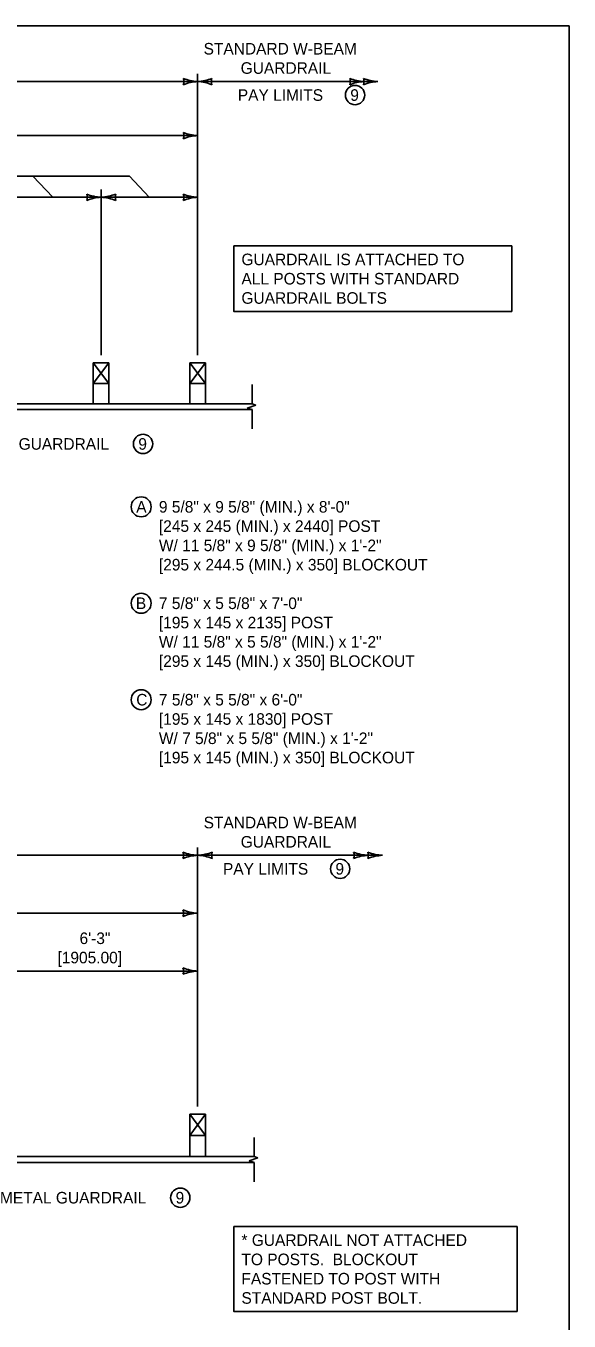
# Model space of a CAD drawing. Extents: x 49991.4 to 50021, y 49987.6 to 50011.4.
# Drawn here: x 50013.94 to 50016.75, y 49992.28 to 49999 of the extents above; entities that cross this region are included whole.
import ezdxf

# ---------------------------------------------------------------- set-up
doc = ezdxf.new("R2010")
doc.units = 0
for name, color, linetype in [('Level 1', 7, 'Continuous'), ('Level 2', 7, 'Continuous'), ('Level 3', 7, 'Continuous'), ('Level 6', 7, 'Continuous')]:
    doc.layers.add(name, color=color, linetype=linetype)

msp = doc.modelspace()

# ---------------------------------------------------------------- linework, layer by layer
at = {"layer": 'Level 1'}
for p, q in [((50014.2865, 49997.2528), (50014.2865, 49997.146)), ((50014.2865, 49997.2528), (50014.3665, 49997.2528)), ((50014.3665, 49997.2528), (50014.2865, 49997.146)), ((50014.2865, 49997.2528), (50014.3665, 49997.146)), ((50014.3665, 49997.2528), (50014.3665, 49997.146)), ((50014.7867, 49997.2528), (50014.7867, 49997.146)), ((50014.7867, 49997.2528), (50014.8668, 49997.2528)), ((50014.8668, 49997.2528), (50014.7867, 49997.146)), ((50014.7867, 49997.2528), (50014.8668, 49997.146)), ((50014.8668, 49997.2528), (50014.8668, 49997.146)), ((50014.2865, 49997.1464), (50014.2865, 49997.0393)), ((50014.2865, 49997.146), (50014.3665, 49997.146)), ((50014.3665, 49997.0393), (50014.3665, 49997.146)), ((50014.7867, 49997.1464), (50014.7867, 49997.0393)), ((50014.7867, 49997.146), (50014.8668, 49997.146)), ((50014.8668, 49997.0393), (50014.8668, 49997.146)), ((50010.7212, 49997.0393), (50015.1097, 49997.0393)), ((50010.6183, 49997.0101), (50015.1097, 49997.0101)), ((50014.8682, 49993.3576), (50014.7856, 49993.3576)), ((50014.7856, 49993.3576), (50014.7856, 49993.1371)), ((50014.7856, 49993.2474), (50014.8682, 49993.3576)), ((50014.7856, 49993.3576), (50014.8682, 49993.2474)), ((50014.8682, 49993.1371), (50014.8682, 49993.3576)), ((50014.7856, 49993.2474), (50014.8682, 49993.2474)), ((50010.1008, 49993.1371), (50015.1199, 49993.1371)), ((50010.1008, 49993.1071), (50015.1199, 49993.1071))]:
    msp.add_line(p, q, dxfattribs=at)
msp.add_lwpolyline([(49999.3835, 49998.9992), (50016.7501, 49998.9992), (50016.7501, 49987.7988), (49999.3835, 49987.7988)], close=True, dxfattribs=at)
at = {"layer": 'Level 2'}
for points in [[(50015.0136, 49997.8586), (50016.4533, 49997.8586), (50016.4533, 49997.5186), (50015.0136, 49997.5186)], [(50015.0136, 49992.7744), (50016.4809, 49992.7744), (50016.4809, 49992.3344), (50015.0136, 49992.3344)]]:
    msp.add_lwpolyline(points, close=True, dxfattribs=at)
for centre, radius in [((50015.6417, 49998.6408), 0.05), ((50014.544, 49996.832), 0.05), ((50014.5344, 49996.506), 0.0517), ((50014.5344, 49996.006), 0.0517), ((50014.5344, 49995.506), 0.0517), ((50015.5648, 49994.6292), 0.05), ((50014.737, 49992.9242), 0.05)]:
    msp.add_circle(centre, radius, dxfattribs=at)
at = {"layer": 'Level 3'}
for p, q in [((50014.8267, 49998.7108), (50010.8246, 49998.7108)), ((50014.8267, 49998.7508), (50014.8267, 49997.2928)), ((50015.7598, 49998.7108), (50014.8267, 49998.7108)), ((50012.3255, 49998.4307), (50014.8267, 49998.4307)), ((50013.5752, 49998.2207), (50014.4732, 49998.2207)), ((50013.9729, 49998.2207), (50014.0763, 49998.1108)), ((50014.4732, 49998.2207), (50014.5766, 49998.1108)), ((50013.8262, 49998.1107), (50014.3265, 49998.1107)), ((50014.3265, 49998.1507), (50014.3265, 49997.2928)), ((50014.3265, 49998.1107), (50014.8267, 49998.1107)), ((50014.8268, 49993.3976), (50014.8268, 49994.7392)), ((50010.7212, 49994.6992), (50014.8268, 49994.6992)), ((50015.7841, 49994.6992), (50014.8268, 49994.6992)), ((50010.978, 49994.3992), (50014.8268, 49994.3992)), ((50013.8004, 49994.0992), (50014.8268, 49994.0992))]:
    msp.add_line(p, q, dxfattribs=at)
for centre, radius, start, end in [((50014.8356, 49998.9273), 0.2167, 247.45601, 267.63952), ((50014.7017, 49998.7108), 0.0534, 342.13882, 17.86118), ((50014.8379, 49998.4839), 0.2271, 92.82731, 112.07716), ((50014.8155, 49998.9376), 0.2271, 272.82731, 292.07716), ((50014.8178, 49998.4942), 0.2167, 67.45601, 87.63952), ((50014.9517, 49998.7108), 0.0534, 162.13882, 197.86118), ((50015.6972, 49998.9273), 0.2167, 247.45601, 267.63952), ((50015.5633, 49998.7108), 0.0534, 342.13882, 17.86118), ((50015.6994, 49998.4839), 0.2271, 92.82731, 112.07716), ((50015.7687, 49998.9273), 0.2167, 247.45601, 267.63952), ((50015.6348, 49998.7108), 0.0534, 342.13882, 17.86118), ((50015.771, 49998.4839), 0.2271, 92.82731, 112.07716), ((50014.8356, 49998.6472), 0.2167, 247.45601, 267.63952), ((50014.7017, 49998.4307), 0.0534, 342.13882, 17.86118), ((50014.8379, 49998.2039), 0.2271, 92.82731, 112.07716), ((50014.3354, 49998.3273), 0.2167, 247.45601, 267.63952), ((50014.2015, 49998.1107), 0.0534, 342.13882, 17.86118), ((50014.3377, 49997.8839), 0.2271, 92.82731, 112.07716), ((50014.315, 49998.3436), 0.2331, 272.82731, 292.07716), ((50014.3173, 49997.8885), 0.2224, 67.45601, 87.63952), ((50014.4547, 49998.1107), 0.0548, 162.13882, 197.86118), ((50014.8356, 49998.3273), 0.2167, 247.45601, 267.63952), ((50014.7017, 49998.1107), 0.0534, 342.13882, 17.86118), ((50014.8379, 49997.8839), 0.2271, 92.82731, 112.07716), ((50014.836, 49994.9214), 0.2223, 247.45601, 267.63952), ((50014.6986, 49994.6992), 0.0548, 342.13882, 17.86118), ((50014.8383, 49994.4665), 0.233, 92.82731, 112.07716), ((50014.8153, 49994.932), 0.233, 272.82731, 292.07716), ((50014.8177, 49994.4771), 0.2223, 67.45601, 87.63952), ((50014.955, 49994.6992), 0.0548, 162.13882, 197.86118), ((50015.7198, 49994.9214), 0.2223, 247.45601, 267.63952), ((50015.5825, 49994.6992), 0.0548, 342.13882, 17.86118), ((50015.7222, 49994.4665), 0.233, 92.82731, 112.07716), ((50015.7933, 49994.9214), 0.2223, 247.45601, 267.63952), ((50015.6559, 49994.6992), 0.0548, 342.13882, 17.86118), ((50015.7956, 49994.4665), 0.233, 92.82731, 112.07716), ((50014.836, 49994.6214), 0.2223, 247.45601, 267.63952), ((50014.6986, 49994.3992), 0.0548, 342.13882, 17.86118), ((50014.8383, 49994.1665), 0.233, 92.82731, 112.07716), ((50014.836, 49994.3214), 0.2223, 247.45601, 267.63952), ((50014.6986, 49994.0992), 0.0548, 342.13882, 17.86118), ((50014.8383, 49993.8665), 0.233, 92.82731, 112.07716)]:
    msp.add_arc(centre, radius, start, end, dxfattribs=at)
at = {"layer": 'Level 6'}
for p, q in [((50015.1097, 49997.0393), (50015.1097, 49997.1393)), ((50015.128, 49997.0328), (50015.0835, 49997.017)), ((50015.1097, 49997.0393), (50015.128, 49997.0328)), ((50015.0835, 49997.017), (50015.1097, 49997.0101)), ((50015.1097, 49997.0101), (50015.1097, 49996.9101)), ((50015.1199, 49993.1371), (50015.1199, 49993.2371)), ((50015.1382, 49993.1306), (50015.0938, 49993.1148)), ((50015.1199, 49993.1371), (50015.1382, 49993.1306)), ((50015.0938, 49993.1148), (50015.1199, 49993.1071)), ((50015.1199, 49993.1071), (50015.1199, 49993.0071))]:
    msp.add_line(p, q, dxfattribs=at)

# ---------------------------------------------------------------- texts
at = {"layer": 'Level 2'}
for s, p in [('STANDARD W-BEAM', (50014.8576, 49998.8508)), ('GUARDRAIL', (50015.0496, 49998.7508)), ('PAY LIMITS', (50015.0348, 49998.6108)), ('9', (50015.6172, 49998.6107)), ('GUARDRAIL IS ATTACHED TO', (50015.0536, 49997.7586)), ('ALL POSTS WITH STANDARD', (50015.0536, 49997.6586)), ('GUARDRAIL BOLTS', (50015.0536, 49997.5586)), ('METAL GUARDRAIL', (50013.61, 49996.802)), ('9', (50014.5196, 49996.802)), ('A', (50014.5087, 49996.476)), ('9 5/8" x 9 5/8" (MIN.) x 8\'-0"', (50014.6262, 49996.476)), ('[245 x 245 (MIN.) x 2440] POST', (50014.6262, 49996.376)), ('W/ 11 5/8" x 9 5/8" (MIN.) x 1\'-2"', (50014.6262, 49996.276)), ('[295 x 244.5 (MIN.) x 350] BLOCKOUT', (50014.6262, 49996.176)), ('B', (50014.5068, 49995.9761)), ('7 5/8" x 5 5/8" x 7\'-0"', (50014.6262, 49995.976)), ('[195 x 145 x 2135] POST ', (50014.6262, 49995.876)), ('W/ 11 5/8" x 5 5/8" (MIN.) x 1\'-2"', (50014.6262, 49995.776)), ('[295 x 145 (MIN.) x 350] BLOCKOUT ', (50014.6262, 49995.676)), ('C', (50014.5089, 49995.476)), ('7 5/8" x 5 5/8" x 6\'-0"', (50014.6262, 49995.476)), ('[195 x 145 x 1830] POST ', (50014.6262, 49995.376)), ('W/ 7 5/8" x 5 5/8" (MIN.) x 1\'-2"', (50014.6262, 49995.276)), ('[195 x 145 (MIN.) x 350] BLOCKOUT', (50014.6262, 49995.176)), ('STANDARD W-BEAM', (50014.8579, 49994.8392)), ('GUARDRAIL', (50015.0498, 49994.7392)), ('PAY LIMITS', (50014.9579, 49994.5992)), ('9', (50015.5403, 49994.5993)), ('6\'-3"', (50014.2153, 49994.2392)), ('[1905.00]', (50014.1009, 49994.1392)), ('METAL GUARDRAIL', (50013.803, 49992.8942)), ('9', (50014.7126, 49992.8942)), ('* GUARDRAIL NOT ATTACHED', (50015.0536, 49992.6744)), ('TO POSTS.  BLOCKOUT', (50015.0536, 49992.5744)), ('FASTENED TO POST WITH', (50015.0536, 49992.4744)), ('STANDARD POST BOLT.', (50015.0536, 49992.3744))]:
    msp.add_text(s, height=0.06, dxfattribs=at).set_placement(p)

doc.saveas('drawing.dxf')
